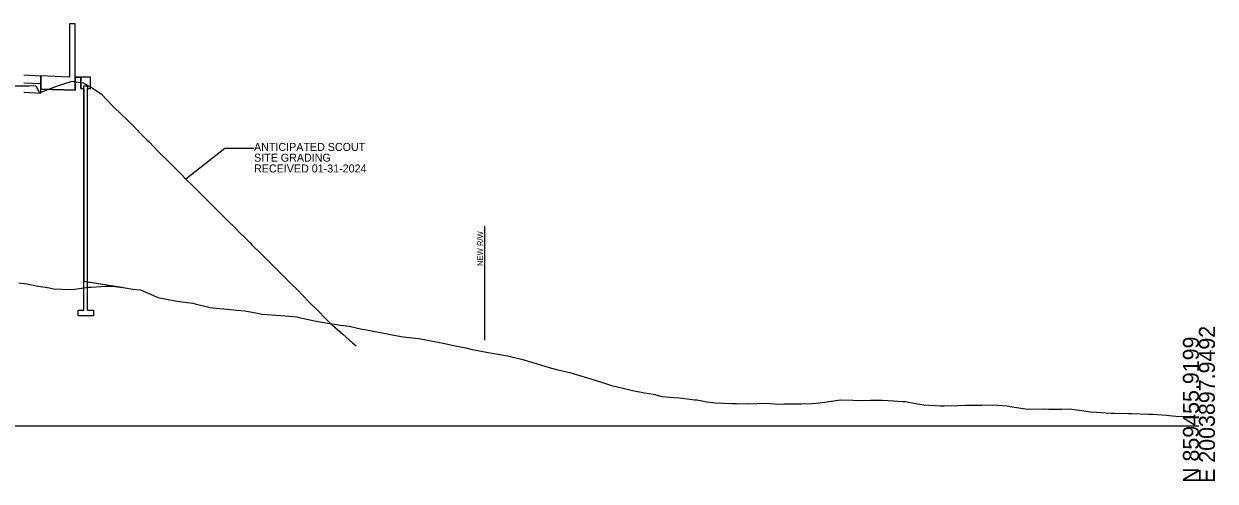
# Model space of a CAD drawing. Extents: x 2004049 to 2067449, y 841632 to 859611.
# Drawn here: x 2061240.9 to 2061449.4, y 846453.8 to 846533.9 of the extents above; entities that cross this region are included whole.
import ezdxf

# ---------------------------------------------------------------- set-up
doc = ezdxf.new("R2010")
doc.units = 0
for name, color, linetype in [('RD_DDB_Profile_Elev', 7, 'Continuous'), ('RD_GPK_XS_Cell', 7, 'Continuous'), ('RD_PD_WallFill', 7, 'Continuous'), ('RD_XS_Base', 7, 'Continuous'), ('RD_XS_Box', 7, 'Continuous'), ('RD_XS_EarthShd', 7, 'Continuous'), ('RD_XS_EwShp1', 7, 'Continuous'), ('RD_XS_ExGround', 7, 'Continuous'), ('RD_XS_MedBWall', 7, 'Continuous'), ('RD_XS_PaveShd', 7, 'Continuous'), ('RD_XS_TX_Box', 7, 'Continuous')]:
    doc.layers.add(name, color=color, linetype=linetype)

msp = doc.modelspace()

# ---------------------------------------------------------------- linework, layer by layer
at = {"layer": 'RD_DDB_Profile_Elev'}
for points in [[(2061239.45, 846523), (2061241.85, 846523.04), (2061242.64, 846523.07), (2061243.07, 846523), (2061243.68, 846521.79), (2061244.97, 846522.3), (2061245.32, 846522.44), (2061245.88, 846522.66), (2061246.86, 846523.03), (2061249.39, 846523.83), (2061250.02, 846523.74), (2061250.51, 846523.66), (2061251.33, 846523.53), (2061253.05, 846522.55), (2061254.56, 846521.53), (2061256.45, 846519.53), (2061258.21, 846517.83), (2061258.77, 846517.28), (2061260.52, 846515.53), (2061261.6, 846514.46), (2061262.54, 846513.53), (2061262.85, 846513.21), (2061264.46, 846511.53), (2061266.46, 846509.53), (2061267.93, 846508.06), (2061268.46, 846507.53), (2061269.31, 846506.68), (2061270.48, 846505.53), (2061272.49, 846503.52), (2061274.49, 846501.53), (2061275.98, 846500.05), (2061276.51, 846499.53), (2061278.02, 846498.02), (2061278.51, 846497.53), (2061279.87, 846496.19), (2061280.54, 846495.53), (2061280.91, 846495.16), (2061282.55, 846493.53), (2061283.75, 846492.32), (2061284.54, 846491.53), (2061285.66, 846490.41), (2061286.56, 846489.53), (2061287.88, 846488.21), (2061288.57, 846487.53), (2061289.9, 846486.15), (2061290.5, 846485.53), (2061290.82, 846485.22), (2061292.58, 846483.53), (2061293.56, 846482.49), (2061294.47, 846481.53), (2061296.74, 846479.53), (2061298.45, 846478.06), (2061299.07, 846477.53)], [(2061281.23, 846512.07), (2061276.11, 846512.07), (2061269.31, 846506.68)]]:
    msp.add_lwpolyline(points, dxfattribs=at)
at = {"layer": 'RD_GPK_XS_Cell'}
msp.add_line((2061196.51, 846463.53), (2061446.51, 846463.53), dxfattribs=at)
at = {"layer": 'RD_PD_WallFill'}
for p, q in [((2061251.44, 846483.75), (2061251.44, 846522.53)), ((2061252.11, 846483.75), (2061252.11, 846522.53))]:
    msp.add_line(p, q, dxfattribs=at)
msp.add_lwpolyline([(2061252.11, 846483.75), (2061253.11, 846483.75), (2061253.11, 846482.75), (2061250.44, 846482.75), (2061250.44, 846483.75), (2061251.44, 846483.75)], dxfattribs=at)
at = {"layer": 'RD_XS_Base'}
for p, q in [((2061243.94, 846521.74), (2061243.94, 846523.41)), ((2061240.94, 846521.89), (2061243.94, 846521.74))]:
    msp.add_line(p, q, dxfattribs=at)
at = {"layer": 'RD_XS_Box'}
msp.add_lwpolyline([(2061252.61, 846522.53), (2061252.61, 846524.53), (2061250.94, 846524.53), (2061250.94, 846522.53), (2061251.44, 846522.53), (2061251.44, 846523.03), (2061252.11, 846523.03), (2061252.11, 846522.53)], close=True, dxfattribs=at)
at = {"layer": 'RD_XS_EarthShd'}
for p, q in [((2061249.94, 846524.53), (2061250.94, 846524.53)), ((2061252.11, 846488.73), (2061258.11, 846487.77))]:
    msp.add_line(p, q, dxfattribs=at)
at = {"layer": 'RD_XS_EwShp1'}
for p, q in [((2061250.94, 846524.53), (2061249.94, 846524.53)), ((2061249.94, 846524.53), (2061249.94, 846522.25)), ((2061250.94, 846522.53), (2061250.94, 846524.53)), ((2061243.94, 846521.74), (2061243.94, 846522.45)), ((2061249.94, 846522.25), (2061243.94, 846522.45)), ((2061250.94, 846522.53), (2061251.44, 846522.53)), ((2061250.94, 846522.53), (2061250.94, 846522.53)), ((2061251.44, 846522.53), (2061251.44, 846488.84)), ((2061240.94, 846521.89), (2061243.94, 846521.74)), ((2061251.44, 846488.84), (2061258.11, 846487.77))]:
    msp.add_line(p, q, dxfattribs=at)
at = {"layer": 'RD_XS_ExGround'}
msp.add_lwpolyline([(2061240.07, 846488.52), (2061241.45, 846488.35), (2061243.11, 846488.01), (2061245.43, 846487.65), (2061246.15, 846487.5), (2061249.19, 846487.37), (2061249.8, 846487.46), (2061252.23, 846487.77), (2061252.71, 846487.79), (2061255.28, 846487.96), (2061256.36, 846487.93), (2061258.32, 846487.75), (2061260, 846487.44), (2061261.36, 846487.3), (2061263.64, 846486.35), (2061264.4, 846485.99), (2061267.44, 846485.38), (2061268.24, 846485.26), (2061270.48, 846484.97), (2061270.92, 846484.85), (2061273.52, 846484.23), (2061274.57, 846484.08), (2061276.56, 846483.94), (2061278.21, 846483.78), (2061279.6, 846483.65), (2061281.85, 846483.26), (2061282.64, 846483.07), (2061285.83, 846482.8), (2061286.68, 846482.75), (2061288.73, 846482.57), (2061289.13, 846482.49), (2061291.77, 846481.87), (2061292.77, 846481.73), (2061294.81, 846481.35), (2061296.42, 846481.13), (2061297.85, 846480.94), (2061300.06, 846480.44), (2061300.89, 846480.32), (2061303.93, 846479.71), (2061305.11, 846479.49), (2061306.97, 846479.16), (2061307.34, 846479.08), (2061310.01, 846478.78), (2061310.98, 846478.61), (2061313.06, 846478.24), (2061314.62, 846477.93), (2061316.1, 846477.58), (2061318.27, 846477.15), (2061319.14, 846476.94), (2061322.18, 846476.35), (2061323.55, 846476.13), (2061325.22, 846475.85), (2061325.55, 846475.77), (2061328.26, 846475.11), (2061329.19, 846474.85), (2061331.3, 846474.2), (2061332.83, 846473.75), (2061334.34, 846473.32), (2061336.47, 846472.83), (2061337.38, 846472.56), (2061340.12, 846471.75), (2061340.65, 846471.59), (2061341.99, 846471.14), (2061343.76, 846470.58), (2061346.51, 846469.91), (2061347.4, 846469.7), (2061349.55, 846469.27), (2061351.04, 846469.06), (2061352.59, 846468.64), (2061354.68, 846468.5), (2061355.63, 846468.44), (2061358.32, 846468.08), (2061358.67, 846468.06), (2061360.43, 846467.74), (2061361.97, 846467.52), (2061364.75, 846467.42), (2061365.61, 846467.43), (2061367.8, 846467.36), (2061369.25, 846467.44), (2061370.84, 846467.51), (2061372.89, 846467.31), (2061373.88, 846467.37), (2061376.53, 846467.37), (2061376.92, 846467.38), (2061378.87, 846467.44), (2061380.18, 846467.52), (2061383, 846467.96), (2061383.82, 846468.04), (2061386.04, 846468.03), (2061387.46, 846467.97), (2061389.08, 846468.03), (2061391.1, 846467.99), (2061392.12, 846467.96), (2061394.74, 846467.78), (2061395.16, 846467.76), (2061397.3, 846467.37), (2061398.38, 846467.21), (2061401.25, 846467.01), (2061402.03, 846466.99), (2061404.29, 846467.06), (2061405.67, 846467.11), (2061407.33, 846467.11), (2061408.52, 846467.13), (2061410.37, 846467.17), (2061412.95, 846467), (2061413.41, 846466.89), (2061415.74, 846466.54), (2061416.59, 846466.41), (2061419.49, 846466.47), (2061420.23, 846466.42), (2061422.53, 846466.45), (2061423.88, 846466.47), (2061425.58, 846466.28), (2061427.52, 846465.98), (2061428.62, 846465.93), (2061431.16, 846465.75), (2061431.66, 846465.71), (2061434.18, 846465.66), (2061434.8, 846465.65), (2061437.74, 846465.58), (2061438.44, 846465.54), (2061440.78, 846465.36), (2061442.46, 846465.23), (2061443.82, 846465.17), (2061445.07, 846465.19), (2061446.51, 846465.09)], dxfattribs=at)
at = {"layer": 'RD_XS_MedBWall'}
msp.add_lwpolyline([(2061249.94, 846522.25), (2061249.94, 846533.86), (2061248.94, 846533.86), (2061248.94, 846524.53), (2061243.94, 846524.78), (2061243.94, 846522.45)], close=True, dxfattribs=at)
at = {"layer": 'RD_XS_PaveShd'}
for p, q in [((2061240.94, 846524.93), (2061243.94, 846524.78)), ((2061243.94, 846523.41), (2061243.94, 846524.78)), ((2061240.94, 846523.56), (2061243.94, 846523.41))]:
    msp.add_line(p, q, dxfattribs=at)
at = {"layer": 'RD_XS_TX_Box'}
msp.add_line((2061321.51, 846498.48), (2061321.51, 846478.48), dxfattribs=at)

# ---------------------------------------------------------------- texts
at = {"layer": 'RD_DDB_Profile_Elev'}
for s, p in [('ANTICIPATED SCOUT', (2061281.22, 846511.62)), ('SITE GRADING', (2061281.22, 846509.74)), ('RECEIVED 01-31-2024', (2061281.22, 846507.85))]:
    msp.add_text(s, height=1.4, dxfattribs=at).set_placement(p)
at = {"layer": 'RD_GPK_XS_Cell'}
for s, p in [('E 2003897.9492', (2061449.31, 846453.53)), ('N 859455.9199', (2061446.51, 846453.53))]:
    msp.add_text(s, height=2.8, rotation=90, dxfattribs=at).set_placement(p)
at = {"layer": 'RD_XS_TX_Box'}
msp.add_text('NEW R/W', height=1, rotation=90, dxfattribs=at).set_placement((2061321.26, 846491.48))

doc.saveas('drawing.dxf')
